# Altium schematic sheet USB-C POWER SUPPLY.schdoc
size 420 x 297 mm; Symbol: Drawing-Symbol_A4; @Project Name: USB-C POWER SUPPLY; @Page Count: 1; @Update Date: 2026-10-12; @Create Date: 2026-10-12; @Schematic Name: Schematic1; @Page No: 1; @Page Name: P1; Company: EasyEDA.com; Version: V1.0; Page Size: A3; Drawn: KHUSHI; Device: Drawing-Symbol_A4; @Create Time: 10:33:24; @Update Time: 10:33:24; Border: 1; Width: 1655; Height: 1170; Region Start: 1; X Region Count: 6; Y Region Count: 4; Blade Width: 10; Title Block Position: 3; @Board Name: Board1
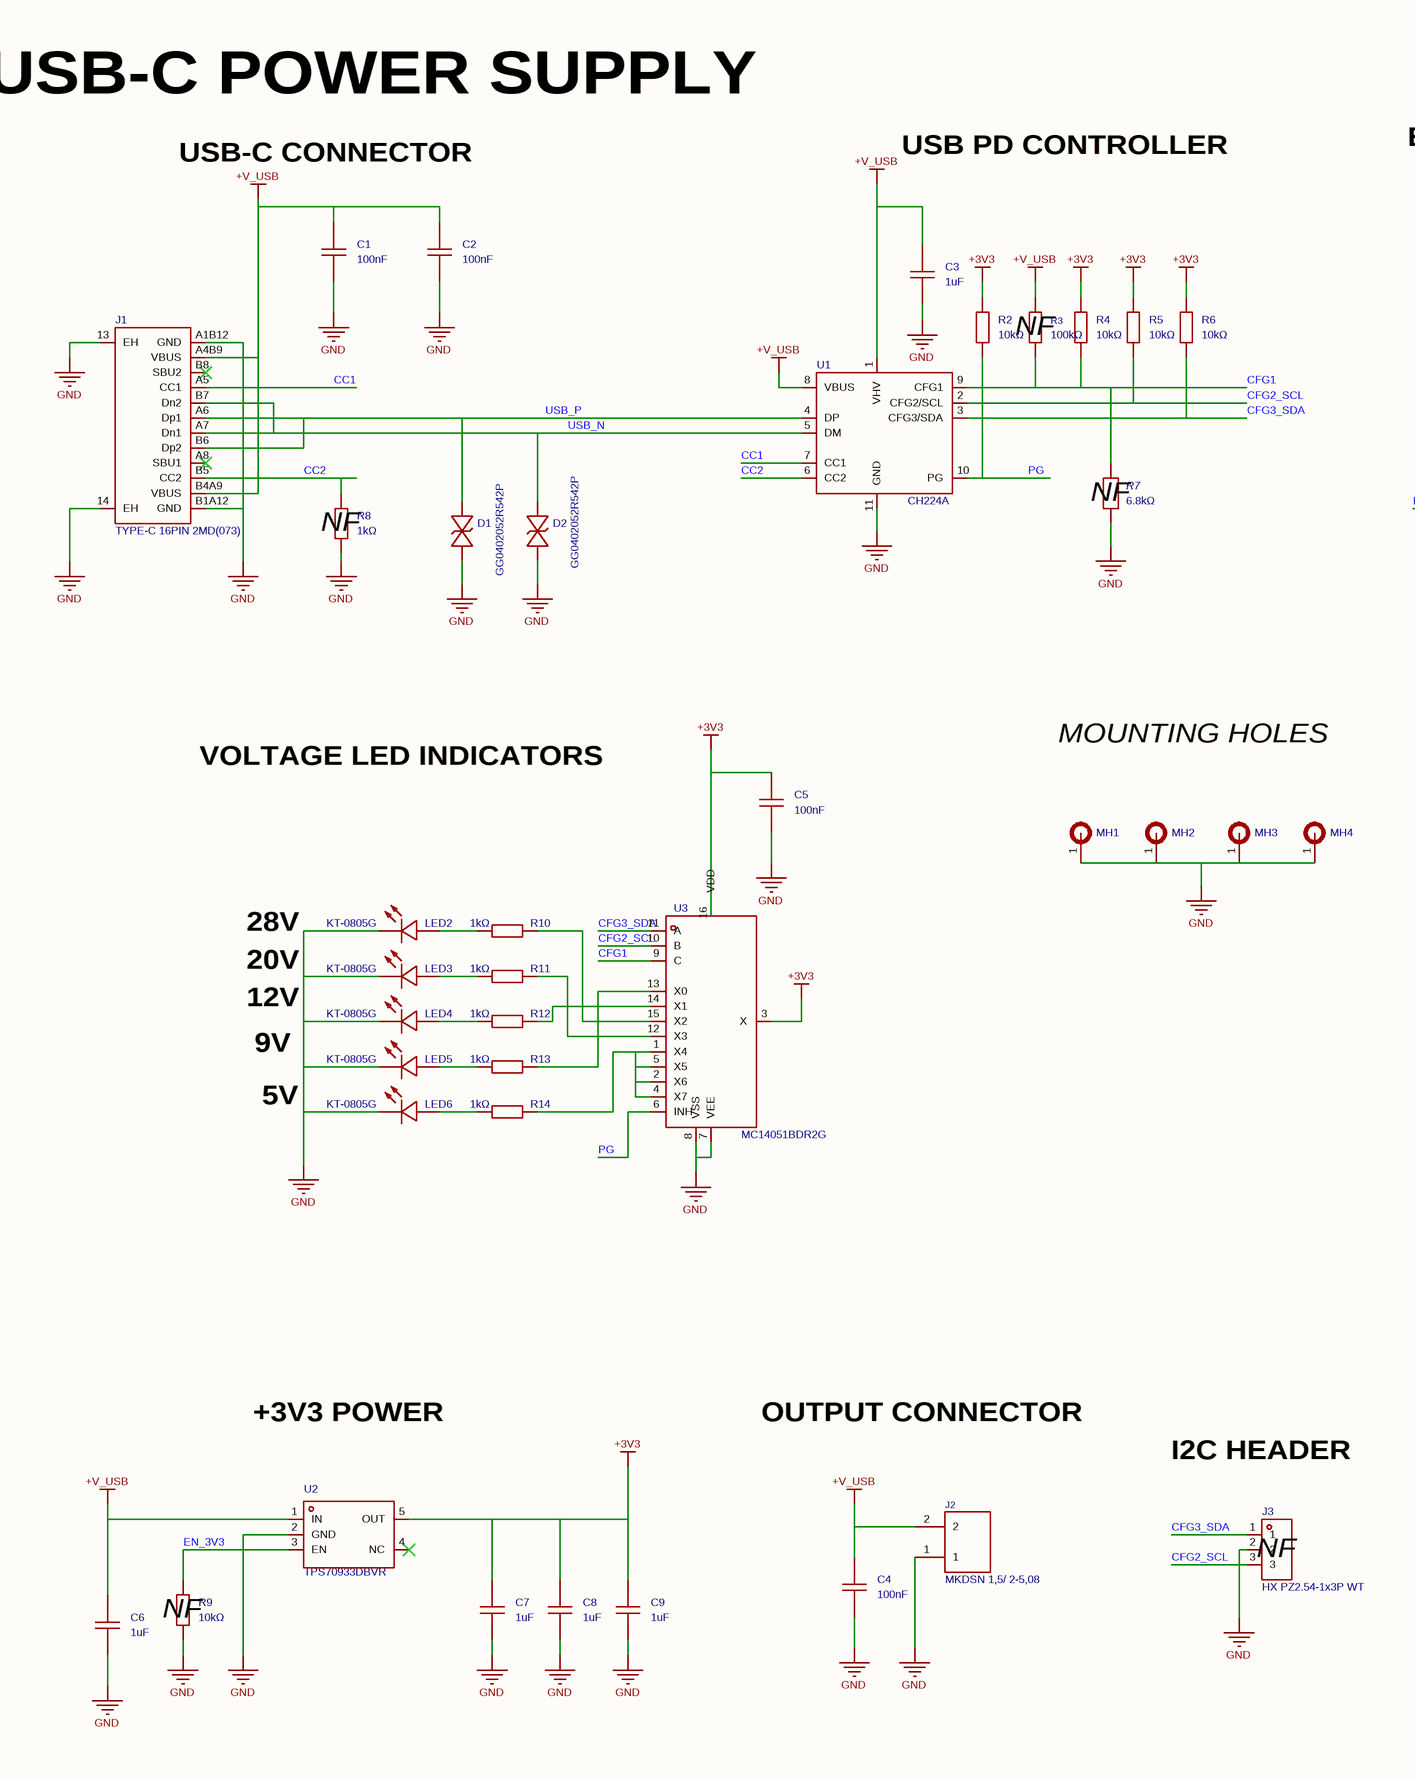
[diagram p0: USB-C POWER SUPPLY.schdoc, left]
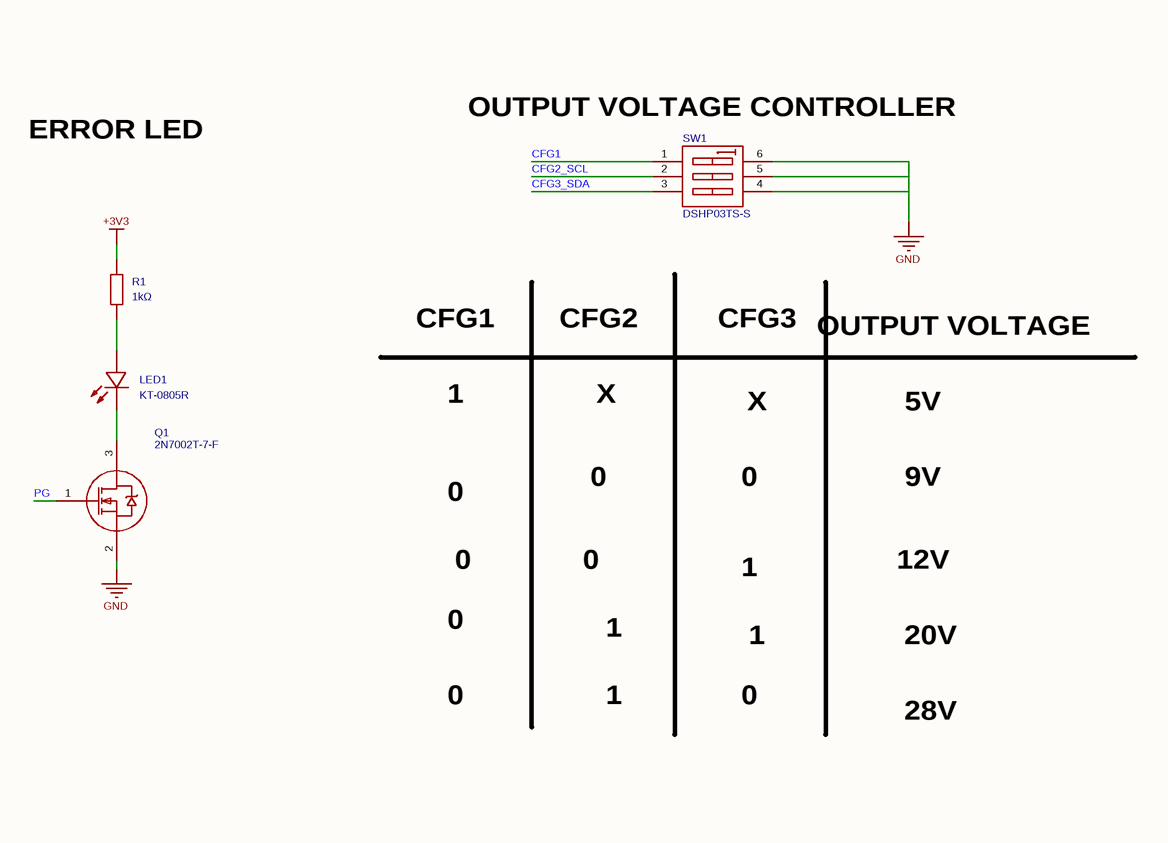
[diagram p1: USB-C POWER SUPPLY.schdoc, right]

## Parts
C1  100nF  [C0402]
C2  100nF  [C0402]
C3  1uF  [C0603]
C4  100nF  [C0402]
C5  100nF  [C0402]
C6  1uF  [C0603]
C7  1uF  [C0603]
C8  1uF  [C0603]
C9  1uF  [C0603]
D1  GG0402052R542P  [D0402-BI]
D2  GG0402052R542P  [D0402-BI]
J1  TYPE-C 16PIN 2MD(073)  [USB-C-SMD_TYPE-C-16PIN-2MD-073]
J2  MKDSN 1,5/ 2-5,08  [CONN-TH_2P-P5.08_1729128]
J3  HX PZ2.54-1x3P WT  [HDR-SMD_3P-P2.54-H-M_KH-2.54PH-1X3P-L13.5-WT]
LED1  KT-0805R  [LED0805-R-RD]
LED2  KT-0805G  [LED0805-R-RD]
LED3  KT-0805G  [LED0805-R-RD]
LED4  KT-0805G  [LED0805-R-RD]
LED5  KT-0805G  [LED0805-R-RD]
LED6  KT-0805G  [LED0805-R-RD]
MH1  (no value)  [MH_7.5MMx2.7MM]
MH2  (no value)  [MH_7.5MMx2.7MM]
MH3  (no value)  [MH_7.5MMx2.7MM]
MH4  (no value)  [MH_7.5MMx2.7MM]
Q1  2N7002T-7-F  [SOT-523-3_L1.6-W0.8-P1.00-LS1.6-BR]
R1  1kΩ  [R0402]
R2  10kΩ  [R0402]
R3  100kΩ  [R0402]
R4  10kΩ  [R0402]
R5  10kΩ  [R0402]
R6  10kΩ  [R0402]
R7  6.8kΩ  [R0402]
R8  1kΩ  [R0402]
R9  10kΩ  [R0402]
R10  1kΩ  [R0402]
R11  1kΩ  [R0402]
R12  1kΩ  [R0402]
R13  1kΩ  [R0402]
R14  1kΩ  [R0402]
SW1  DSHP03TS-S  [SW-SMD_DSHP03TS-S]
U1  CH224A  [ESSOP-10_L4.9-W3.9-P1.0-LS6.0-TL-EP]
U2  TPS70933DBVR  [SOT-23-5_L3.0-W1.7-P0.95-LS2.8-BR]
U3  MC14051BDR2G  [SOIC-16_L9.9-W3.9-P1.27-LS6.0-BL]

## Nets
+3V3: C5.1 C7.2 C8.2 C9.2 R1.1 R2.1 R4.1 R5.1 R6.1 U2.5(OUT) U3.3(X) U3.16(VDD)
+V_USB: C1.1 C2.1 C3.2 C4.1 C6.2 J1.A4B9(VBUS) J1.B4A9(VBUS) J2.2 R3.1 U1.1(VHV) U1.8(VBUS) U2.1(IN)
GND: C1.2 C2.2 C3.1 C4.2 C5.2 C6.1 C7.1 C8.1 C9.1 D1.2 D2.1 J1.13(EH) J1.14(EH) J1.A1B12(GND) J1.B1A12(GND) J2.1 J3.2 LED2.2(K) LED3.2(K) LED4.2(K) LED5.2(K) LED6.2(K) MH1.1 MH2.1 MH3.1 MH4.1 Q1.2(S) R7.2 R8.2 R9.2 SW1.4 SW1.5 SW1.6 U1.11(GND) U2.2(GND) U3.7(VEE) U3.8(VSS)
CC1: J1.A5(CC1) U1.7(CC1)
CC2: J1.B5(CC2) R8.1 U1.6(CC2)
CFG1: R3.2 R4.2 R7.1 SW1.1 U1.9(CFG1) U3.9(C)
CFG2_SCL: J3.3 R5.2 SW1.2 U1.2(CFG2/SCL) U3.10(B)
CFG3_SDA: J3.1 R6.2 SW1.3 U1.3(CFG3/SDA) U3.11(A)
EN_3V3: R9.1 U2.3(EN)
PG: Q1.1(G) R2.2 U1.10(PG) U3.6(INH)
USB_N: D2.2 J1.A7(Dn1) J1.B7(Dn2) U1.5(DM)
USB_P: D1.1 J1.A6(Dp1) J1.B6(Dp2) U1.4(DP)
NetLED1_1: LED1.1(A) R1.2
NetLED1_2: LED1.2(K) Q1.3(D)
NetLED2_1: LED2.1(A) R10.1
NetLED3_1: LED3.1(A) R11.1
NetLED4_1: LED4.1(A) R12.1
NetLED5_1: LED5.1(A) R13.1
NetLED6_1: LED6.1(A) R14.1
NetR10_2: R10.2 U3.15(X2)
NetR11_2: R11.2 U3.12(X3)
NetR12_2: R12.2 U3.14(X1)
NetR13_2: R13.2 U3.13(X0)
NetR14_2: R14.2 U3.1(X4) U3.2(X6) U3.4(X7) U3.5(X5)

Not connected (* = marked no-connect by the designer): J1 A8(SBU1)* B8(SBU2)*; U2 4(NC)*

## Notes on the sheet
- USB-C POWER SUPPLY
- (near SW1) OUTPUT VOLTAGE CONTROLLER
- USB-C CONNECTOR
- USB PD CONTROLLER
- ERROR LED
- (near R3) NF
- CFG1
- CFG2
- CFG3
- OUTPUT VOLTAGE
- 1
- X
- 5V
- (near R7) NF
- 0
- 9V
- (near R8) NF
- 12V
- 20V
- MOUNTING HOLES
- 28V
- VOLTAGE LED INDICATORS
- +3V3 POWER
- OUTPUT CONNECTOR
- I2C HEADER
- (near J3) NF
- (near R9) NF

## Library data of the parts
C1 C2 C4 C5 = CL05B104KB54PNC: Capacitance:100nF Tolerance:±10% Tolerance:±10% Voltage Rating:50V Temperature Coefficient:X7R; Manufacturer: SAMSUNG(三星); AddInBom: yes; ModelId: b7d13df3e9464d7a99d0651d1a5b4d570819f05c4eef4c71ace90d822a990e87; ModelName: C0402_L1.0-W0.5-H0.5; ModelTransform: 39.37,19.685,0,0,0,0,0,0,0; Tolerance: ±10%; Voltage Rating: 50V; Temperature Coefficient: X7R
C3 C6-C9 = CL10B105KB8NQNC: Capacitance:1uF Tolerance:±10% Tolerance:±10% Voltage Rating:50V Temperature Coefficient:X7R; Manufacturer: SAMSUNG(三星); AddInBom: yes; ModelId: 624118aa3cc7497086c383c2d72e08520819f05c4eef4c71ace90d822a990e87; ModelName: C0603_L1.6-W0.8-H0.8; ModelTransform: 62.992,31.496,0,0,0,0,0,0,0; Tolerance: ±10%; Voltage Rating: 50V; Temperature Coefficient: X7R
D1 D2 = GG0402052R542P: Reverse Stand-Off Voltage (Vrwm):5V Clamping Voltage:15.5V Peak Pulse Current (Ipp):3A@8/20us Peak Pulse Power Dissipation (Ppp):46W@8/20us Voltage - Breakdown:5.5V Reverse Leakage Current (Ir):100nA Operating Temperature:-55℃~+125℃ Operating Temperature:; Manufacturer: Kyocera AVX; AddInBom: yes; ModelId: 9d627b6ad13249ab8e6fe12f8c614d230819f05c4eef4c71ace90d822a990e87; ModelName: D0402_L1.0-W0.5-H0.5; ModelTransform: 39.37,19.685,0,0,0,0,0,0,0; Reverse Stand-Off Voltage (Vrwm): 5V; Clamping Voltage: 15.5V; Voltage - Breakdown: 5.5V; Reverse Leakage Current (Ir): 100nA; level of protection: IEC 61000-4-4；IEC 61000-4-2; Type: ESD; Junction Capacitance: 2.5pF
J1 = TYPE-C 16PIN 2MD(073): Connector Type:Type-C Protocol Standard:- Gender:Female Mounting Type:Surface Mount, Right Angle Number of Contacts:16P Number of Ports:1 Current Rating-Power:3A Voltage Rating:5V Connect-Disconnect Life:10 thousand cycles Supplementary Features:- Center; Manufacturer: SHOU HAN(首韩); AddInBom: yes; ModelId: e7514eef573e45b68df9e9a6124b25320819f05c4eef4c71ace90d822a990e87; ModelName: USB-C-SMD_TYPE-C-6PIN-2MD-073; ModelTransform: 351.9678,298.4246,0,0,0,0,0,-47.244,-35.433; Gender: Female; Number of Contacts: 16P; Number of Ports: 1; Current Rating-Power: 3A; Voltage Rating: 5V; Detection color: Black
J2 = MKDSN 1,5/ 2-5,08: Connector Type:Board Side/Plug Termination Style:Without fixing device Number of Positions or Pins:1x2P Pitch:5.08mm Color:Green Mounting Type:Through Hole Number of Pins:2P Number of Rows:1 Number of PINs Per Row:2 Current Rating:13.5A Voltage Rating (Ma; Manufacturer: Phoenix Contact(菲尼克斯); AddInBom: yes; ModelId: e94b0705da6446fbb8beff0ba3aaa1620819f05c4eef4c71ace90d822a990e87; ModelTransform: 400,303.655,0,180,0,0,10.236,0,-137.795; Number of Positions or Pins: 1x2P; Pitch: 5.08mm; Number of PINs Per Row: 2; Current Rating: 13.5A; Voltage Rating (Max): 400V; Outlet Direction (Vertical Basis): Horizontal Termination
J3 = HX PZ2.54-1x3P WT: Pin Structure:1x3P Pitch:2.54mm Row Spacing:- Circluar Pins/Square Pins:Pin Header Mounting Type:Surface Mount, Right Angle Number of Rows:1 Number of Pins:3P Current Rating:3A Voltage Rating (Max):1kV Length of Mating Pin:6mm Insulation Height:2.5mm Leng; Manufacturer: hanxia(韩下); Add into BOM: no; ConvertToPcb: yes; Pin Structure: 1x3P; Pitch: 2.54mm; Current Rating: 3A; Voltage Rating (Max): 1kV
LED1 = KT-0805R: Manufacturer: KENTO; Symbol: E6C0805UR; AddInBom: yes; ModelId: 167045bb0eae412b9d5564860e113a910819f05c4eef4c71ace90d822a990e87; ModelName: LED0805-RD; ModelTransform: 79.527,49.2125,0,0,0,0,0,0,0
LED2-LED6 = KT-0805G: Lamp Holder Type:2mm x 1.25mm square LED Illumination Color:Emerald Green Voltage - Forward(Vf):2.6V~3.1V Voltage - Forward(Vf):2.6V~3.1V Power(Watts):100mW Forward Current:5mA Wavelength - Dominant:513nm~528nm Wavelength - Dominant:513nm~528nm Peak Wavel; Manufacturer: KENTO; Symbol: 0805G (Green); AddInBom: yes; ModelId: 167045bb0eae412b9d5564860e113a910819f05c4eef4c71ace90d822a990e87; ModelName: LED0805-RD; ModelTransform: 79.527,49.2125,0,0,0,0,0,0,0; Power(Watts): 100mW; Forward Current: 5mA; Peak Wavelength: 525nm; Diode Configuration: Discrete Diode; Lens Color: Water Clear; Luminous Intensity: 430mcd; Viewing Angle: 120°
MH1-MH4 = MH_7.5MMx2.7MM: Add into BOM: no; ConvertToPcb: yes
Q1 = 2N7002T-7-F: Number:1 N-channel Drain to Source Voltage:60V Current - Continuous Drain(Id):115mA RDS(on):13.5Ω@10V Pd - Power Dissipation:150mW Gate Threshold Voltage (Vgs(th)):2V Gate Charge(Qg):- Input Capacitance(Ciss):50pF Reverse Transfer Capacitance (Crss@Vds):5; Manufacturer: DIODES(美台); AddInBom: yes; ModelId: 1cc59aa5ffe4420193f3c1f87584e8b70819f05c4eef4c71ace90d822a990e87; ModelName: SOT-523-3P_L1.6-W0.8-H0.9-LS1.6-P0.50; ModelTransform: 63.48633,62.992,0,180,0,0,0,0,0; Drain to Source Voltage: 60V; Current - Continuous Drain(Id): 115mA; Pd - Power Dissipation: 150mW; Gate Threshold Voltage (Vgs(th)): 2V; Input Capacitance(Ciss): 50pF; Reverse Transfer Capacitance (Crss@Vds): 5pF; Output Capacitance(Coss): 25pF; Vgs: ±20V
R1 R10-R14 = 0402WGF1001TCE: Type:Thick Film Resistor Resistance:1kΩ Tolerance:±1% Tolerance:±1% Power(Watts):62.5mW Voltage-Supply(Max):50V Temperature Coefficient:±100ppm/℃ Temperature Coefficient:±100ppm/℃ Operating Temperature:-55℃~+155℃ Operating Temperature:-55℃~+155℃; Manufacturer: UNI-ROYAL(厚声); Add into BOM: yes; ModelId: efdecb7dae4442949d28eecaf748420f0819f05c4eef4c71ace90d822a990e87; ModelName: R0402_L1.0-W0.5-H0.4; ModelTransform: 39.37,19.685,0,0,0,0,0,0,0; Tolerance: ±1%; Power(Watts): 62.5mW; Voltage-Supply(Max): 50V
R2 R4-R6 = 0402WGF1002TCE: Type:Thick Film Resistor Resistance:10kΩ Tolerance:±1% Tolerance:±1% Power(Watts):62.5mW Voltage-Supply(Max):50V Temperature Coefficient:±100ppm/℃ Temperature Coefficient:±100ppm/℃ Operating Temperature:-55℃~+155℃ Operating Temperature:-55℃~+155℃; Manufacturer: UNI-ROYAL(厚声); AddInBom: yes; ModelId: efdecb7dae4442949d28eecaf748420f0819f05c4eef4c71ace90d822a990e87; ModelName: R0402_L1.0-W0.5-H0.4; ModelTransform: 39.37,19.685,0,0,0,0,0,0,0; Tolerance: ±1%; Power(Watts): 62.5mW; Voltage-Supply(Max): 50V
R3 = 0402WGF1003TCE: Type:Thick Film Resistor Resistance:100kΩ Tolerance:±1% Tolerance:±1% Power(Watts):62.5mW Voltage-Supply(Max):50V Temperature Coefficient:±100ppm/℃ Temperature Coefficient:±100ppm/℃ Operating Temperature:-55℃~+155℃ Operating Temperature:-55℃~+155℃; Manufacturer: UNI-ROYAL(厚声); Add into BOM: no; ConvertToPcb: yes; ModelId: efdecb7dae4442949d28eecaf748420f0819f05c4eef4c71ace90d822a990e87; ModelName: R0402_L1.0-W0.5-H0.4; ModelTransform: 39.37,19.685,0,0,0,0,0,0,0; Tolerance: ±1%; Power(Watts): 62.5mW; Voltage-Supply(Max): 50V
R7 = NQ02WGF6801TCE: Type:Thick Film Resistor Resistance:6.8kΩ Tolerance:±1% Tolerance:±1% Power(Watts):62.5mW Voltage-Supply(Max):100V Temperature Coefficient:±100ppm/℃ Temperature Coefficient:±100ppm/℃ Operating Temperature:-55℃~+155℃ Operating Temperature:-55℃~+155℃; Manufacturer: UNI-ROYAL(厚声); Add into BOM: no; ConvertToPcb: yes; ModelId: efdecb7dae4442949d28eecaf748420f0819f05c4eef4c71ace90d822a990e87; ModelName: R0402_L1.0-W0.5-H0.4; ModelTransform: 39.37,19.685,0,0,0,0,0,0,0; Tolerance: ±1%; Power(Watts): 62.5mW; Voltage-Supply(Max): 100V
R8 = 0402WGF1001TCE: Type:Thick Film Resistor Resistance:1kΩ Tolerance:±1% Tolerance:±1% Power(Watts):62.5mW Voltage-Supply(Max):50V Temperature Coefficient:±100ppm/℃ Temperature Coefficient:±100ppm/℃ Operating Temperature:-55℃~+155℃ Operating Temperature:-55℃~+155℃; Manufacturer: UNI-ROYAL(厚声); Add into BOM: no; ConvertToPcb: yes; ModelId: efdecb7dae4442949d28eecaf748420f0819f05c4eef4c71ace90d822a990e87; ModelName: R0402_L1.0-W0.5-H0.4; ModelTransform: 39.37,19.685,0,0,0,0,0,0,0; Tolerance: ±1%; Power(Watts): 62.5mW; Voltage-Supply(Max): 50V
R9 = 0402WGF1002TCE: Type:Thick Film Resistor Resistance:10kΩ Tolerance:±1% Tolerance:±1% Power(Watts):62.5mW Voltage-Supply(Max):50V Temperature Coefficient:±100ppm/℃ Temperature Coefficient:±100ppm/℃ Operating Temperature:-55℃~+155℃ Operating Temperature:-55℃~+155℃; Manufacturer: UNI-ROYAL(厚声); Add into BOM: no; ConvertToPcb: yes; ModelId: efdecb7dae4442949d28eecaf748420f0819f05c4eef4c71ace90d822a990e87; ModelName: R0402_L1.0-W0.5-H0.4; ModelTransform: 39.37,19.685,0,0,0,0,0,0,0; Tolerance: ±1%; Power(Watts): 62.5mW; Voltage-Supply(Max): 50V
SW1 = DSHP03TS-S: Type:Slide, Recessed Circuit:SPST Number of Positions:3 Termination Style:Gull Wing Lead Pitch:1.27mm Current Rating:25mA Voltage Rating:24V Operating Temperature:-20℃~+70℃ Operating Temperature:-20℃~+70℃ Operating Life:3,000 Cycles Color:Black; Manufacturer: XKB Connection(中国星坤); AddInBom: yes; ModelId: ef8092e631bd432089e4baaae7a95b740819f05c4eef4c71ace90d822a990e87; ModelName: SW-SMD_6P-L5.4-W5.4-H2.3-LS8.4-P1.27; ModelTransform: 212.9917,328.7395,0,180,0,0,0.197,0.005,0; Circuit: SPST; Number of Positions: 3; Current Rating: 25mA; Voltage Rating: 24V
U1 = CH224A-RF: Type:Power Receiver Controller Output Power:140W Output Voltage:5V；20V；15V；12V；28V；9V Operating Temperature:-40℃~+105℃ Operating Temperature:-40℃~+105℃; Manufacturer: WCH(南京沁恒); AddInBom: yes; ModelId: caddd54494d446ce85a816aa480d5ff10819f05c4eef4c71ace90d822a990e87; ModelTransform: 192.913,236.22,0,0,0,0,0,0,0; Output Power: 140W
U2 = TPS70933DBVR: Output Configuration:Positive Voltage - Supply:30V Output Voltage:3.3V Output Voltage:3.3V Output Current:150mA Power Supply Rejection Ratio (PSRR):80dB@(10Hz) Voltage Dropout:960mV@(150mA) standby current:1.4uA Noise:190uVrms Features:Over Current Protec; Manufacturer: TI(德州仪器); AddInBom: yes; ModelId: 3168b22659ce4998ae232d44bb704e0a0819f05c4eef4c71ace90d822a990e87; ModelName: SOT-23-5_L2.9-W1.6-H1.1-LS2.8-P0.95; ModelTransform: 114.173,109.636,0,180,0,0,0,0,0; Voltage - Supply: 30V; Output Voltage: 3.3V; standby current: 1.4uA; Output Type: Fixed; Number of Outputs: 1
U3 = MC14051BDR2G-RF: Switch Circuit:8:1 Number of Channels:1 Ron:250Ω Voltage - Supply:3V~18V Voltage - Supply:3V~18V Bandwidth:17MHz Operating Temperature:-55℃~+125℃ Operating Temperature:-55℃~+125℃ Propagation Delay (tpd):15ns Features:Level shifting；Fault protection; Manufacturer: onsemi(安森美); AddInBom: yes; ModelId: 9adfdf34b7774b23880141fd3e8b4dbb0819f05c4eef4c71ace90d822a990e87; ModelName: SOIC-16_L9.9-W3.9-H1.8-LS6.0-P1.27; ModelTransform: 389.763,236.454,0,0,0,0,0,0,0; Switch Circuit: 8:1; Number of Channels: 1; Ron: 250Ω; Voltage - Supply: 3V~18V; Bandwidth: 17MHz; Propagation Delay (tpd): 15ns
